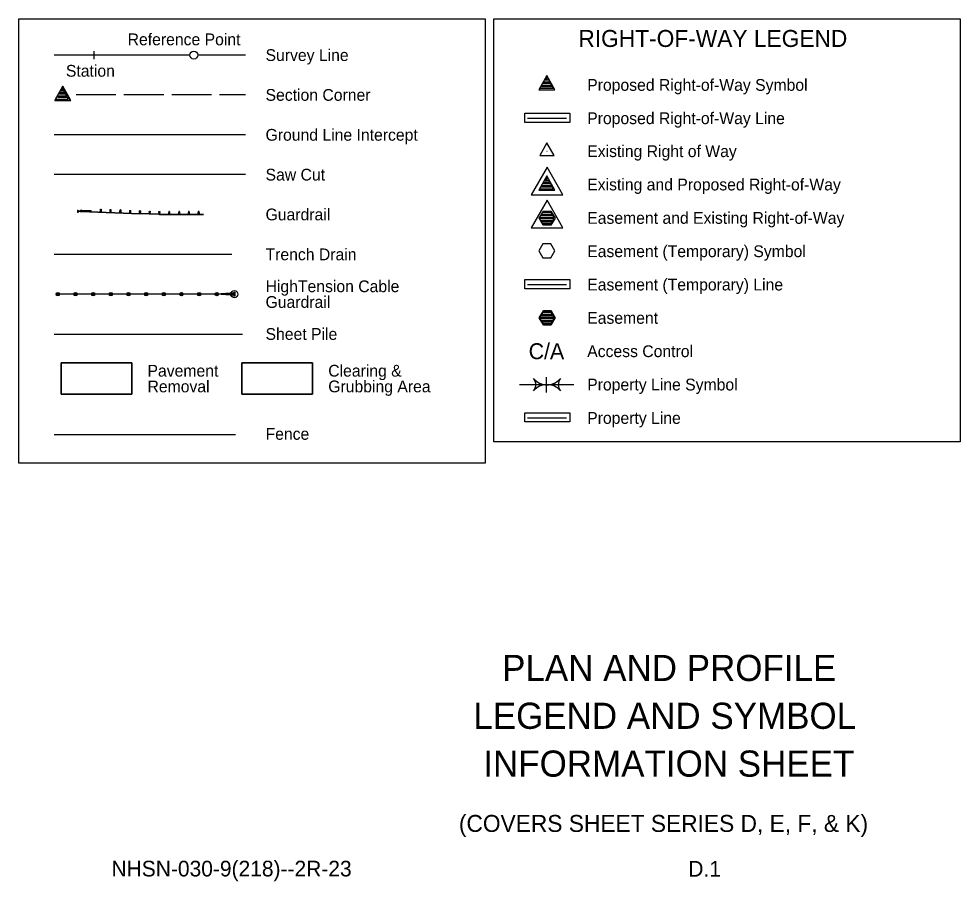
# Model space of a CAD drawing. Extents: x 0.53 to 2.71, y 0.07 to 1.78.
# Drawn here: x 1.712 to 2.712, y 0.073 to 0.99 of the extents above; entities that cross this region are included whole.
import ezdxf

# ---------------------------------------------------------------- set-up
doc = ezdxf.new("R2010")
doc.units = 0
for name, color, linetype in [('Barrier', 7, 'Continuous'), ('ClearGrub', 7, 'Continuous'), ('Default', 7, 'Continuous'), ('DisROW Property Lines', 7, 'Continuous'), ('Drainage', 7, 'Continuous'), ('dsnGroundLineIntercept', 7, 'Continuous'), ('dsnTextFinalPlan', 7, 'Continuous'), ('dsnTextShtTitle', 7, 'Continuous'), ('Entrance', 7, 'Continuous'), ('Fence', 7, 'Continuous'), ('Removals', 7, 'Continuous'), ('ROW Property Lines', 7, 'Continuous'), ('ROWAreas', 7, 'Continuous'), ('rowdsnSymbolsTE', 7, 'Continuous'), ('RowExisting', 7, 'Continuous'), ('ROWLines', 7, 'Continuous'), ('Sawcut', 7, 'Continuous'), ('Section Lines', 7, 'Continuous'), ('SheetPile', 7, 'Continuous'), ('SheetText', 7, 'Continuous'), ('SurAlignment', 7, 'Continuous'), ('Text', 7, 'Continuous')]:
    doc.layers.add(name, color=color, linetype=linetype)

msp = doc.modelspace()

# ---------------------------------------------------------------- linework, layer by layer
at = {"layer": 'Barrier'}
for p, q in [((1.7795, 0.7853), (1.7774, 0.7854)), ((1.7774, 0.7849), (1.7795, 0.7848)), ((1.7785, 0.7849), (1.7785, 0.7854)), ((1.7785, 0.7854), (1.8409, 0.7829)), ((1.7785, 0.7849), (1.8409, 0.7824)), ((1.779, 0.7864), (1.7885, 0.786)), ((1.779, 0.7848), (1.779, 0.7854)), ((1.7887, 0.785), (1.7894, 0.785)), ((1.7999, 0.7873), (1.799, 0.7862)), ((1.7991, 0.7874), (1.7998, 0.7862)), ((1.7995, 0.7875), (1.7995, 0.7875)), ((1.8103, 0.7869), (1.8094, 0.7858)), ((1.8095, 0.7869), (1.8102, 0.7858)), ((1.8099, 0.7871), (1.8099, 0.7871)), ((1.8207, 0.7865), (1.8198, 0.7854)), ((1.8199, 0.7865), (1.8207, 0.7854)), ((1.8203, 0.7867), (1.8203, 0.7867)), ((1.8204, 0.7865), (1.8204, 0.7865)), ((1.8311, 0.7861), (1.8302, 0.785)), ((1.8303, 0.7861), (1.8311, 0.785)), ((1.8307, 0.7863), (1.8307, 0.7863)), ((1.8415, 0.7857), (1.8406, 0.7846)), ((1.8407, 0.7857), (1.8415, 0.7845)), ((1.8618, 0.7821), (1.8409, 0.7829)), ((1.8617, 0.7816), (1.8409, 0.7824)), ((1.8411, 0.7858), (1.8411, 0.7858)), ((1.8519, 0.7852), (1.851, 0.7842)), ((1.8519, 0.7841), (1.851, 0.7842)), ((1.851, 0.7842), (1.851, 0.7825)), ((1.851, 0.7825), (1.8518, 0.7825)), ((1.8511, 0.7853), (1.8519, 0.7841)), ((1.8515, 0.7854), (1.8515, 0.7854)), ((1.8518, 0.7825), (1.8519, 0.7841)), ((1.8622, 0.7848), (1.8613, 0.7837)), ((1.8613, 0.7848), (1.8622, 0.7837)), ((1.8622, 0.7837), (1.8613, 0.7837)), ((1.8613, 0.7837), (1.8613, 0.7821)), ((1.8613, 0.7821), (1.8622, 0.7821)), ((1.8617, 0.7816), (1.8669, 0.7816)), ((1.8618, 0.785), (1.8618, 0.785)), ((1.8618, 0.7821), (1.8669, 0.7821)), ((1.8622, 0.7821), (1.8622, 0.7837)), ((1.8669, 0.7821), (1.8878, 0.7821)), ((1.8669, 0.7816), (1.8878, 0.7816)), ((1.8717, 0.7848), (1.8726, 0.7837)), ((1.8726, 0.7848), (1.8717, 0.7837)), ((1.8717, 0.7837), (1.8726, 0.7837)), ((1.8717, 0.7821), (1.8717, 0.7837)), ((1.8726, 0.7821), (1.8717, 0.7821)), ((1.8722, 0.785), (1.8722, 0.785)), ((1.8726, 0.7837), (1.8726, 0.7821)), ((1.8822, 0.7848), (1.883, 0.7837)), ((1.883, 0.7848), (1.8822, 0.7837)), ((1.8822, 0.7837), (1.883, 0.7837)), ((1.8822, 0.7821), (1.8822, 0.7837)), ((1.883, 0.7821), (1.8822, 0.7821)), ((1.8826, 0.785), (1.8826, 0.785)), ((1.883, 0.7837), (1.883, 0.7821)), ((1.8878, 0.7821), (1.9086, 0.7821)), ((1.8878, 0.7816), (1.9086, 0.7816)), ((1.8926, 0.7848), (1.8934, 0.7837)), ((1.8934, 0.7848), (1.8926, 0.7837)), ((1.8926, 0.7837), (1.8934, 0.7837)), ((1.8926, 0.7821), (1.8926, 0.7837)), ((1.8934, 0.7821), (1.8926, 0.7821)), ((1.893, 0.785), (1.893, 0.785)), ((1.8934, 0.7837), (1.8934, 0.7821)), ((1.903, 0.7848), (1.9038, 0.7837)), ((1.9038, 0.7848), (1.903, 0.7837)), ((1.903, 0.7837), (1.9038, 0.7837)), ((1.903, 0.7821), (1.903, 0.7837)), ((1.9038, 0.7821), (1.903, 0.7821)), ((1.9034, 0.785), (1.9034, 0.785)), ((1.9038, 0.7837), (1.9038, 0.7821)), ((1.9414, 0.6971), (1.7539, 0.6971)), ((1.9414, 0.6986), (1.9226, 0.6971)), ((1.9414, 0.6956), (1.9226, 0.6971)), ((1.9414, 0.6986), (1.9414, 0.6971)), ((1.9414, 0.6971), (1.9414, 0.6956))]:
    msp.add_line(p, q, dxfattribs=at)
for points in [[(1.7751, 0.786), (1.7748, 0.786)], [(1.7748, 0.786), (1.7748, 0.784)], [(1.7748, 0.784), (1.7751, 0.7841), (1.775, 0.786), (1.7748, 0.786)], [(1.7751, 0.784), (1.7748, 0.784)], [(1.7763, 0.7854), (1.7751, 0.786)], [(1.7751, 0.784), (1.7751, 0.786)], [(1.7774, 0.7854), (1.7751, 0.7854)], [(1.7774, 0.7849), (1.7751, 0.7848)], [(1.7763, 0.7849), (1.7751, 0.784)], [(1.7795, 0.7854), (1.7774, 0.7854), (1.7774, 0.7849), (1.7795, 0.7848)], [(1.7781, 0.7854), (1.779, 0.7864)], [(1.7781, 0.7854), (1.7782, 0.7864)], [(1.7781, 0.7854), (1.779, 0.7854)], [(1.779, 0.7854), (1.7782, 0.7864)], [(1.7782, 0.7864), (1.779, 0.7864)], [(1.779, 0.7864), (1.7783, 0.7864)], [(1.779, 0.7864), (1.7783, 0.7864)], [(1.7783, 0.7864), (1.7783, 0.7864)], [(1.7783, 0.7854), (1.7789, 0.7854)], [(1.779, 0.7854), (1.7783, 0.7854)], [(1.779, 0.7854), (1.7783, 0.7854)], [(1.779, 0.7864), (1.7885, 0.786)], [(1.779, 0.7854), (1.779, 0.7864)], [(1.779, 0.786), (1.779, 0.7864)], [(1.779, 0.786), (1.779, 0.7864)], [(1.779, 0.786), (1.7885, 0.7856)], [(1.779, 0.786), (1.7885, 0.7856)], [(1.779, 0.7855), (1.779, 0.786)], [(1.779, 0.7855), (1.779, 0.786)], [(1.779, 0.7854), (1.779, 0.7855)], [(1.779, 0.7854), (1.779, 0.7855)], [(1.779, 0.7855), (1.779, 0.7855)], [(1.779, 0.7855), (1.779, 0.7855)], [(1.7795, 0.7848), (1.7799, 0.7848), (1.7799, 0.7853), (1.7795, 0.7854)], [(1.7885, 0.785), (1.7894, 0.786)], [(1.7885, 0.7851), (1.7885, 0.786)], [(1.7885, 0.7851), (1.7886, 0.786)], [(1.7885, 0.785), (1.7885, 0.7851)], [(1.7885, 0.785), (1.7885, 0.7851)], [(1.7885, 0.785), (1.7894, 0.785)], [(1.7885, 0.785), (1.7894, 0.785)], [(1.7894, 0.785), (1.7886, 0.786)], [(1.7886, 0.786), (1.7894, 0.786)], [(1.7886, 0.786), (1.7894, 0.786)], [(1.7894, 0.785), (1.7894, 0.786)], [(1.799, 0.7846), (1.7999, 0.7845)], [(1.7995, 0.7874), (1.7995, 0.7875), (1.7994, 0.7875), (1.7994, 0.7874)], [(1.7995, 0.7873), (1.7995, 0.7874), (1.7994, 0.7874), (1.7994, 0.7873)], [(1.8095, 0.7842), (1.8103, 0.7841)], [(1.8099, 0.787), (1.8099, 0.7871), (1.8098, 0.7871), (1.8098, 0.787)], [(1.8099, 0.7869), (1.8099, 0.787), (1.8098, 0.787), (1.8098, 0.7869)], [(1.8203, 0.7865), (1.8203, 0.7866), (1.8202, 0.7866), (1.8202, 0.7865)], [(1.8203, 0.7866), (1.8203, 0.7867), (1.8203, 0.7867), (1.8203, 0.7866)], [(1.8303, 0.7833), (1.8311, 0.7833)], [(1.8307, 0.7861), (1.8308, 0.7862), (1.8306, 0.7862), (1.8306, 0.7861)], [(1.8307, 0.7862), (1.8307, 0.7863), (1.8307, 0.7863), (1.8307, 0.7862)], [(1.8412, 0.7857), (1.8412, 0.7857), (1.841, 0.7857), (1.841, 0.7857)], [(1.8411, 0.7857), (1.8411, 0.7858), (1.8411, 0.7858), (1.8411, 0.7857)], [(1.8515, 0.7853), (1.8515, 0.7854), (1.8515, 0.7854), (1.8515, 0.7853)], [(1.8516, 0.7853), (1.8516, 0.7853), (1.8515, 0.7853), (1.8515, 0.7853)], [(1.8618, 0.7849), (1.8618, 0.785), (1.8617, 0.785), (1.8617, 0.7849)], [(1.8618, 0.7848), (1.8618, 0.7849), (1.8617, 0.7849), (1.8617, 0.7848)], [(1.8721, 0.7849), (1.8721, 0.785), (1.8722, 0.785), (1.8722, 0.7849)], [(1.8721, 0.7848), (1.8721, 0.7849), (1.8722, 0.7849), (1.8722, 0.7848)], [(1.8825, 0.7849), (1.8825, 0.785), (1.8826, 0.785), (1.8826, 0.7849)], [(1.8825, 0.7848), (1.8825, 0.7849), (1.8826, 0.7849), (1.8826, 0.7848)], [(1.8929, 0.7848), (1.8929, 0.7849), (1.893, 0.7849), (1.893, 0.7848)], [(1.893, 0.7849), (1.893, 0.785), (1.893, 0.785), (1.893, 0.7849)], [(1.9034, 0.7849), (1.9034, 0.785), (1.9034, 0.785), (1.9034, 0.7849)], [(1.9034, 0.7848), (1.9034, 0.7849), (1.9035, 0.7849), (1.9035, 0.7848)]]:
    msp.add_lwpolyline(points, dxfattribs=at)
for points in [[(1.7795, 0.7854), (1.7795, 0.7854), (1.7799, 0.7854), (1.7799, 0.7853), (1.7799, 0.7848), (1.7799, 0.7847), (1.7795, 0.7847), (1.7795, 0.7848)], [(1.7998, 0.7845), (1.7989, 0.7846), (1.799, 0.7862), (1.7998, 0.7862)], [(1.7998, 0.7862), (1.799, 0.7862), (1.7991, 0.7874), (1.7999, 0.7873)], [(1.8102, 0.7841), (1.8093, 0.7842), (1.8094, 0.7858), (1.8102, 0.7858)], [(1.8102, 0.7858), (1.8094, 0.7858), (1.8095, 0.7869), (1.8103, 0.7869)], [(1.8207, 0.7854), (1.8198, 0.7854), (1.8199, 0.7865), (1.8207, 0.7865)], [(1.8206, 0.7837), (1.8198, 0.7837), (1.8198, 0.7854), (1.8207, 0.7854)], [(1.8311, 0.785), (1.8302, 0.785), (1.8303, 0.7861), (1.8311, 0.7861)], [(1.831, 0.7833), (1.8302, 0.7833), (1.8302, 0.785), (1.8311, 0.785)], [(1.8415, 0.7845), (1.8406, 0.7846), (1.8407, 0.7857), (1.8415, 0.7857)], [(1.8414, 0.7829), (1.8406, 0.7829), (1.8406, 0.7846), (1.8415, 0.7845)], [(1.8519, 0.7841), (1.851, 0.7842), (1.8511, 0.7853), (1.8519, 0.7852)], [(1.8622, 0.7837), (1.8613, 0.7837), (1.8613, 0.7848), (1.8622, 0.7848)], [(1.8717, 0.7837), (1.8726, 0.7837), (1.8726, 0.7848), (1.8717, 0.7848)], [(1.8822, 0.7837), (1.883, 0.7837), (1.883, 0.7848), (1.8822, 0.7848)], [(1.8926, 0.7837), (1.8934, 0.7837), (1.8934, 0.7848), (1.8926, 0.7848)], [(1.903, 0.7837), (1.9038, 0.7837), (1.9038, 0.7848), (1.903, 0.7848)], [(1.7535, 0.6979), (1.7542, 0.6979), (1.7542, 0.6963), (1.7535, 0.6963)], [(1.7723, 0.6979), (1.7729, 0.6979), (1.7729, 0.6963), (1.7723, 0.6963)], [(1.791, 0.6979), (1.7917, 0.6979), (1.7917, 0.6963), (1.791, 0.6963)], [(1.8098, 0.6979), (1.8104, 0.6979), (1.8104, 0.6963), (1.8098, 0.6963)], [(1.8285, 0.6979), (1.8292, 0.6979), (1.8292, 0.6963), (1.8285, 0.6963)], [(1.8473, 0.6979), (1.8479, 0.6979), (1.8479, 0.6963), (1.8473, 0.6963)], [(1.866, 0.6979), (1.8667, 0.6979), (1.8667, 0.6963), (1.866, 0.6963)], [(1.8848, 0.6979), (1.8854, 0.6979), (1.8854, 0.6963), (1.8848, 0.6963)], [(1.9035, 0.6979), (1.9042, 0.6979), (1.9042, 0.6963), (1.9035, 0.6963)], [(1.9223, 0.6979), (1.9229, 0.6979), (1.9229, 0.6963), (1.9223, 0.6963)], [(1.941, 0.6993), (1.9417, 0.6993), (1.9417, 0.6949), (1.941, 0.6949)]]:
    msp.add_lwpolyline(points, close=True, dxfattribs=at)
for centre, radius in [((1.9414, 0.6971), 0.00375), ((1.7539, 0.6971), 0.00187), ((1.7726, 0.6971), 0.00187), ((1.7914, 0.6971), 0.00187), ((1.8101, 0.6971), 0.00187), ((1.8289, 0.6971), 0.00187), ((1.8476, 0.6971), 0.00187), ((1.8664, 0.6971), 0.00187), ((1.8851, 0.6971), 0.00187), ((1.9039, 0.6971), 0.00187), ((1.9226, 0.6971), 0.00187)]:
    msp.add_circle(centre, radius, dxfattribs=at)
for centre, radius, start, end in [((1.779, 0.7864), 0.0000347, 357.7147, 87.7147), ((1.779, 0.7864), 0.00000862, 357.7147, 87.7147), ((1.779, 0.7854), 0.0000347, 267.7147, 357.7147), ((1.779, 0.7854), 0.00000862, 267.7147, 357.7147), ((1.7886, 0.786), 0.0000347, 87.7147, 177.7147), ((1.7885, 0.785), 0.0000347, 177.7147, 267.7147)]:
    msp.add_arc(centre, radius, start, end, dxfattribs=at)
at = {"layer": 'ClearGrub'}
msp.add_lwpolyline([(1.9494, 0.6241), (2.0244, 0.6241), (2.0244, 0.5907), (1.9494, 0.5907)], close=True, dxfattribs=at)
at = {"layer": 'Default'}
for points in [[(2.2498, 0.8893), (2.2979, 0.8893), (2.2979, 0.8796), (2.2498, 0.8796)], [(2.2498, 0.7126), (2.2979, 0.7126), (2.2979, 0.7029), (2.2498, 0.7029)], [(2.2498, 0.5709), (2.2979, 0.5709), (2.2979, 0.5613), (2.2498, 0.5613)]]:
    msp.add_lwpolyline(points, close=True, dxfattribs=at)
at = {"layer": 'DisROW Property Lines'}
msp.add_line((2.2529, 0.5656), (2.2941, 0.5656), dxfattribs=at)
at = {"layer": 'Drainage'}
msp.add_line((1.7501, 0.7394), (1.9387, 0.7394), dxfattribs=at)
at = {"layer": 'dsnGroundLineIntercept'}
msp.add_line((1.9533, 0.8664), (1.7501, 0.8664), dxfattribs=at)
at = {"layer": 'dsnTextFinalPlan'}
msp.add_lwpolyline([(1.9494, 0.5907), (2.0244, 0.5907), (2.0244, 0.6241), (1.9494, 0.6241)], close=True, dxfattribs=at)
at = {"layer": 'dsnTextShtTitle'}
for points in [[(1.7124, 0.9896), (2.2078, 0.9896), (2.2078, 0.5177), (1.7124, 0.5177), (1.7124, 0.9896)], [(2.217, 0.9896), (2.7124, 0.9896), (2.7124, 0.5402), (2.217, 0.5402), (2.217, 0.9896)]]:
    msp.add_lwpolyline(points, dxfattribs=at)
at = {"layer": 'Fence'}
msp.add_line((1.7501, 0.5479), (1.9427, 0.5479), dxfattribs=at)
at = {"layer": 'Removals'}
for points in [[(1.7575, 0.5907), (1.8325, 0.5907), (1.8325, 0.6241), (1.7575, 0.6241)], [(1.7575, 0.6241), (1.8325, 0.6241), (1.8325, 0.5907), (1.7575, 0.5907)]]:
    msp.add_lwpolyline(points, close=True, dxfattribs=at)
at = {"layer": 'ROW Property Lines'}
for p, q in [((2.302, 0.6007), (2.2441, 0.6007)), ((2.2731, 0.6007), (2.2731, 0.6089)), ((2.2731, 0.5926), (2.2731, 0.6007)), ((2.2731, 0.6007), (2.2731, 0.6007)), ((2.2732, 0.6008), (2.2732, 0.6008))]:
    msp.add_line(p, q, dxfattribs=at)
for centre, radius, start, end in [((2.2518, 0.601), 0.00984, 318.4601, 40.9346), ((2.2735, 0.5817), 0.0192, 41.3024, 138.4245), ((2.2735, 0.6194), 0.0186, 219.9762, 319.7474), ((2.2956, 0.601), 0.0102, 140.9797, 220.8297)]:
    msp.add_arc(centre, radius, start, end, dxfattribs=at)
at = {"layer": 'ROWAreas'}
msp.add_lwpolyline([(2.2696, 0.6646), (2.2653, 0.6719), (2.2696, 0.6792), (2.278, 0.6792), (2.2823, 0.6719), (2.278, 0.6646), (2.2696, 0.6646), (2.269, 0.6658), (2.2783, 0.6658), (2.2792, 0.6675), (2.2682, 0.6675), (2.2673, 0.6692), (2.28, 0.6692), (2.2809, 0.6709), (2.2665, 0.6709), (2.2656, 0.6717), (2.2665, 0.6725), (2.2809, 0.6725), (2.2817, 0.6717), (2.28, 0.6742), (2.2673, 0.6742), (2.2682, 0.6759), (2.2792, 0.6759), (2.2783, 0.6776), (2.269, 0.6776)], dxfattribs=at)
at = {"layer": 'rowdsnSymbolsTE'}
msp.add_lwpolyline([(2.2696, 0.6646), (2.278, 0.6646), (2.2823, 0.6719), (2.278, 0.6792), (2.2696, 0.6792), (2.2653, 0.6719)], close=True, dxfattribs=at)
at = {"layer": 'RowExisting'}
for points in [[(2.2658, 0.8445), (2.2811, 0.8445), (2.2734, 0.8577)], [(2.2566, 0.8027), (2.2904, 0.8027), (2.2735, 0.8321)], [(2.2566, 0.7677), (2.2904, 0.7677), (2.2735, 0.7971)]]:
    msp.add_lwpolyline(points, close=True, dxfattribs=at)
msp.add_lwpolyline([(2.2734, 0.8489), (2.2735, 0.8489)], dxfattribs=at)
at = {"layer": 'ROWLines'}
for p, q in [((2.2529, 0.8839), (2.2941, 0.8839)), ((2.2529, 0.7073), (2.2941, 0.7073))]:
    msp.add_line(p, q, dxfattribs=at)
for points in [[(2.2648, 0.9141), (2.2817, 0.9141), (2.2733, 0.9294), (2.2648, 0.9141), (2.2665, 0.9158), (2.28, 0.9158), (2.2792, 0.9175), (2.2673, 0.9175), (2.2682, 0.9192), (2.2783, 0.9192), (2.2775, 0.9209), (2.269, 0.9209), (2.2699, 0.9226), (2.2766, 0.9226), (2.2758, 0.9243), (2.2707, 0.9243), (2.2724, 0.926), (2.2741, 0.926), (2.2733, 0.9277)], [(2.2648, 0.8074), (2.2817, 0.8074), (2.2733, 0.8227), (2.2648, 0.8074), (2.2665, 0.8091), (2.28, 0.8091), (2.2792, 0.8108), (2.2673, 0.8108), (2.2682, 0.8125), (2.2783, 0.8125), (2.2775, 0.8142), (2.269, 0.8142), (2.2707, 0.8159), (2.2766, 0.8159), (2.2758, 0.8176), (2.2716, 0.8176), (2.2724, 0.8193), (2.2741, 0.8193), (2.2733, 0.821)], [(2.2693, 0.7704), (2.265, 0.7778), (2.2693, 0.7851), (2.2777, 0.7851), (2.282, 0.7778), (2.2777, 0.7704), (2.2693, 0.7704), (2.269, 0.772), (2.2783, 0.772), (2.2792, 0.7737), (2.2682, 0.7737), (2.2673, 0.7754), (2.28, 0.7754), (2.2809, 0.7771), (2.2656, 0.7771), (2.2656, 0.7788), (2.2809, 0.7788), (2.28, 0.7805), (2.2673, 0.7805), (2.2682, 0.7822), (2.2792, 0.7822), (2.2775, 0.7839), (2.269, 0.7839)]]:
    msp.add_lwpolyline(points, dxfattribs=at)
msp.add_lwpolyline([(2.2692, 0.7358), (2.2776, 0.7358), (2.2819, 0.7431), (2.2776, 0.7505), (2.2692, 0.7505), (2.2649, 0.7431)], close=True, dxfattribs=at)
at = {"layer": 'Sawcut'}
msp.add_line((1.9533, 0.8241), (1.7501, 0.8241), dxfattribs=at)
at = {"layer": 'Section Lines'}
for p, q in [((1.8156, 0.9087), (1.7733, 0.9087)), ((1.8664, 0.9087), (1.8241, 0.9087)), ((1.9172, 0.9087), (1.8749, 0.9087)), ((1.9533, 0.9087), (1.9257, 0.9087))]:
    msp.add_line(p, q, dxfattribs=at)
msp.add_lwpolyline([(1.7505, 0.903), (1.7674, 0.903), (1.7589, 0.9177)], close=True, dxfattribs=at)
msp.add_lwpolyline([(1.7506, 0.9027), (1.7675, 0.9027), (1.759, 0.9179), (1.7506, 0.9027), (1.7531, 0.9044), (1.7649, 0.9044), (1.7641, 0.9061), (1.7539, 0.9061), (1.7548, 0.9078), (1.7633, 0.9078), (1.7624, 0.9095), (1.7556, 0.9095), (1.7565, 0.9112), (1.7616, 0.9112), (1.7607, 0.9129), (1.7573, 0.9129), (1.7582, 0.9146), (1.7599, 0.9146), (1.759, 0.9163)], dxfattribs=at)
at = {"layer": 'SheetPile'}
msp.add_line((1.7501, 0.6547), (1.95, 0.6547), dxfattribs=at)
at = {"layer": 'SurAlignment'}
for p, q in [((1.8941, 0.9511), (1.7501, 0.9511)), ((1.7925, 0.9468), (1.7925, 0.9553)), ((1.9533, 0.9511), (1.9025, 0.9511))]:
    msp.add_line(p, q, dxfattribs=at)
msp.add_circle((1.8983, 0.9511), 0.00423, dxfattribs=at)

# ---------------------------------------------------------------- texts
at = {"layer": 'Entrance'}
msp.add_text('C/A', height=0.01693, dxfattribs=at).set_placement((2.254, 0.628))
at = {"layer": 'SheetText'}
for s, height, p in [('NHSN-030-9(218)--2R-23', 0.016667, (1.8108, 0.0785)), ('D.1', 0.01667, (2.4236, 0.0783))]:
    msp.add_text(s, height=height, dxfattribs=at).set_placement(p)
at = {"layer": 'Text'}
for s, height, p in [('Reference Point', 0.0125, (1.828, 0.9615)), ('RIGHT-OF-WAY LEGEND', 0.018056, (2.3068, 0.9597)), ('Survey Line', 0.0125, (1.9745, 0.9448)), ('Station', 0.0125, (1.7624, 0.9281)), ('Proposed Right-of-Way Symbol', 0.0125, (2.3162, 0.9131)), ('Section Corner', 0.0125, (1.9745, 0.9025)), ('Proposed Right-of-Way Line', 0.0125, (2.3162, 0.8777)), ('Ground Line Intercept', 0.0125, (1.9745, 0.8601)), ('Existing Right of Way', 0.0125, (2.3162, 0.8427)), ('Saw Cut', 0.0125, (1.9745, 0.8178)), ('Existing and Proposed Right-of-Way', 0.0125, (2.3162, 0.8073)), ('Guardrail', 0.0125, (1.9745, 0.7755)), ('Easement and Existing Right-of-Way', 0.0125, (2.3162, 0.7718)), ('Trench Drain', 0.0125, (1.9745, 0.7331)), ('Easement (Temporary) Symbol', 0.0125, (2.3162, 0.7364)), ('HighTension Cable ', 0.0125, (1.9745, 0.6992)), ('Easement (Temporary) Line', 0.0125, (2.3162, 0.701)), ('Guardrail', 0.0125, (1.9745, 0.6825)), ('Easement', 0.0125, (2.3162, 0.6656)), ('Sheet Pile', 0.0125, (1.9745, 0.6485)), ('Access Control', 0.0125, (2.3162, 0.6302)), ('Pavement ', 0.0125, (1.8491, 0.6095)), ('Clearing & ', 0.0125, (2.0411, 0.6095)), ('Removal', 0.0125, (1.8491, 0.5928)), ('Grubbing Area', 0.0125, (2.0411, 0.5928)), ('Property Line Symbol', 0.0125, (2.3162, 0.5948)), ('Property Line', 0.0125, (2.3162, 0.5593)), ('Fence', 0.0125, (1.9745, 0.5424)), ('PLAN AND PROFILE', 0.027778, (2.2258, 0.2861)), ('LEGEND AND SYMBOL', 0.027778, (2.1952, 0.2353)), ('INFORMATION SHEET', 0.027778, (2.2058, 0.1845)), ('(COVERS SHEET SERIES D, E, F, & K)', 0.018056, (2.1799, 0.1258))]:
    msp.add_text(s, height=height, dxfattribs=at).set_placement(p)

doc.saveas('drawing.dxf')
